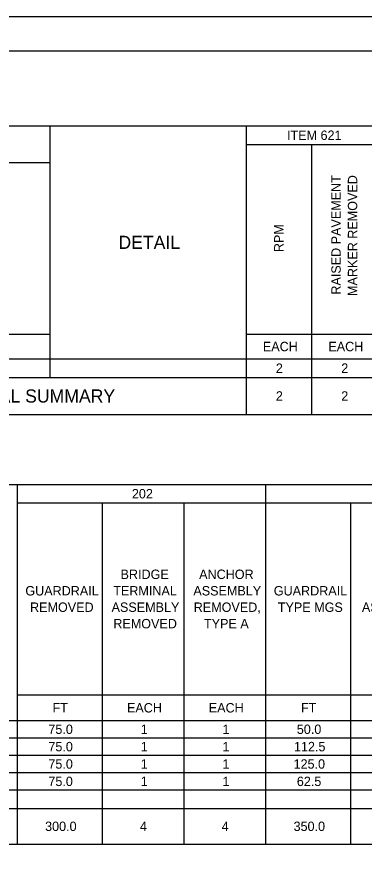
# Model space of a CAD drawing. Extents: x 0 to 34, y 0 to 22.
# Drawn here: x 8.69 to 13.79, y 9.63 to 22 of the extents above; entities that cross this region are included whole.
import ezdxf

# ---------------------------------------------------------------- set-up
doc = ezdxf.new("R2010")
doc.units = 0
for name, color, linetype in [('SH_Border', 7, 'Continuous'), ('SH_Cut_Line', 7, 'Continuous'), ('SH_Text', 7, 'Continuous')]:
    doc.layers.add(name, color=color, linetype=linetype)

msp = doc.modelspace()

# ---------------------------------------------------------------- linework, layer by layer
at = {"layer": 'SH_Border'}
msp.add_lwpolyline([(1.5, 21.5), (33.5, 21.5), (33.5, 0.5), (1.5, 0.5)], close=True, dxfattribs=at)
at = {"layer": 'SH_Cut_Line'}
msp.add_lwpolyline([(0, 0), (34, 0), (34, 22), (0, 22)], close=True, dxfattribs=at)
at = {"layer": 'SH_Text'}
for p, q in [((2.506, 20.4), (9.178, 20.4)), ((9.178, 20.4), (23.578, 20.4)), ((9.178, 20.4), (9.178, 18.852)), ((12.058, 20.4), (12.058, 18.852)), ((12.058, 20.124), (13.978, 20.124)), ((13.018, 20.124), (13.018, 18.852)), ((2.506, 19.86), (9.178, 19.86)), ((9.178, 18.852), (9.178, 16.704)), ((12.058, 18.852), (12.058, 16.164)), ((13.018, 18.852), (13.018, 16.164)), ((5.386, 17.34), (9.178, 17.34)), ((12.058, 17.34), (23.578, 17.34)), ((2.506, 16.98), (9.178, 16.98)), ((9.178, 16.98), (23.578, 16.98)), ((2.506, 16.704), (9.178, 16.704)), ((9.178, 16.704), (23.578, 16.704)), ((2.506, 16.164), (9.178, 16.164)), ((9.178, 16.164), (23.578, 16.164)), ((2.549, 15.134), (22.379, 15.134)), ((8.699, 15.134), (8.699, 9.854)), ((12.344, 15.134), (12.344, 9.854)), ((8.699, 14.864), (19.004, 14.864)), ((9.944, 14.864), (9.944, 9.854)), ((11.144, 14.864), (11.144, 9.854)), ((13.589, 14.864), (13.589, 9.854)), ((8.699, 12.044), (19.004, 12.044)), ((2.549, 11.669), (22.379, 11.669)), ((2.549, 11.414), (22.379, 11.414)), ((2.549, 11.159), (22.379, 11.159)), ((2.549, 10.904), (22.379, 10.904)), ((2.549, 10.649), (22.379, 10.649)), ((2.549, 10.379), (22.379, 10.379)), ((2.549, 9.854), (22.379, 9.854))]:
    msp.add_line(p, q, dxfattribs=at)

# ---------------------------------------------------------------- texts
for s, height, p in [('ITEM 621', 0.138, (12.658, 20.193)), ('DETAIL', 0.1932, (10.185, 18.593)), ('EACH', 0.138, (12.304, 17.091)), ('EACH', 0.138, (13.264, 17.091)), ('2', 0.138, (12.494, 16.773)), ('2', 0.138, (13.454, 16.773)), ('TOTALS CARRIED TO GENERAL SUMMARY', 0.1932, (4.768, 16.337)), ('2', 0.138, (12.494, 16.365)), ('2', 0.138, (13.454, 16.365)), ('202', 0.138, (10.382, 14.93)), ('BRIDGE ', 0.138, (10.216, 13.747)), ('ANCHOR ', 0.138, (11.369, 13.747)), ('GUARDRAIL ', 0.138, (8.819, 13.505)), ('TERMINAL ', 0.138, (10.109, 13.505)), ('ASSEMBLY ', 0.138, (11.284, 13.505)), ('GUARDRAIL ', 0.138, (12.464, 13.505)), ('REMOVED', 0.138, (8.888, 13.264)), ('ASSEMBLY ', 0.138, (10.084, 13.264)), ('REMOVED,', 0.138, (11.289, 13.264)), ('TYPE MGS', 0.138, (12.523, 13.264)), ('ASSEMBLY,', 0.138, (13.757, 13.264)), ('REMOVED', 0.138, (10.11, 13.022)), ('TYPE A', 0.138, (11.44, 13.022)), ('FT', 0.138, (9.218, 11.787)), ('EACH', 0.138, (10.31, 11.787)), ('EACH', 0.138, (11.51, 11.787)), ('FT', 0.138, (12.863, 11.787)), ('75.0', 0.138, (9.157, 11.472)), ('1', 0.138, (10.512, 11.472)), ('1', 0.138, (11.712, 11.472)), ('50.0', 0.138, (12.802, 11.472)), ('75.0', 0.138, (9.157, 11.217)), ('1', 0.138, (10.512, 11.217)), ('1', 0.138, (11.712, 11.217)), ('112.5', 0.138, (12.76, 11.217)), ('75.0', 0.138, (9.157, 10.962)), ('1', 0.138, (10.512, 10.962)), ('1', 0.138, (11.712, 10.962)), ('125.0', 0.138, (12.754, 10.962)), ('75.0', 0.138, (9.157, 10.707)), ('1', 0.138, (10.512, 10.707)), ('1', 0.138, (11.712, 10.707)), ('62.5', 0.138, (12.802, 10.707)), ('300.0', 0.138, (9.109, 10.047)), ('4', 0.138, (10.5, 10.047)), ('4', 0.138, (11.7, 10.047)), ('350.0', 0.138, (12.754, 10.047))]:
    msp.add_text(s, height=height, dxfattribs=at).set_placement(p)
for s, p in [('RAISED PAVEMENT                 ', (13.446, 17.922)), ('MARKER REMOVED', (13.688, 17.902)), ('RPM', (12.607, 18.546))]:
    msp.add_text(s, height=0.138, rotation=90, dxfattribs=at).set_placement(p)

doc.saveas('drawing.dxf')
